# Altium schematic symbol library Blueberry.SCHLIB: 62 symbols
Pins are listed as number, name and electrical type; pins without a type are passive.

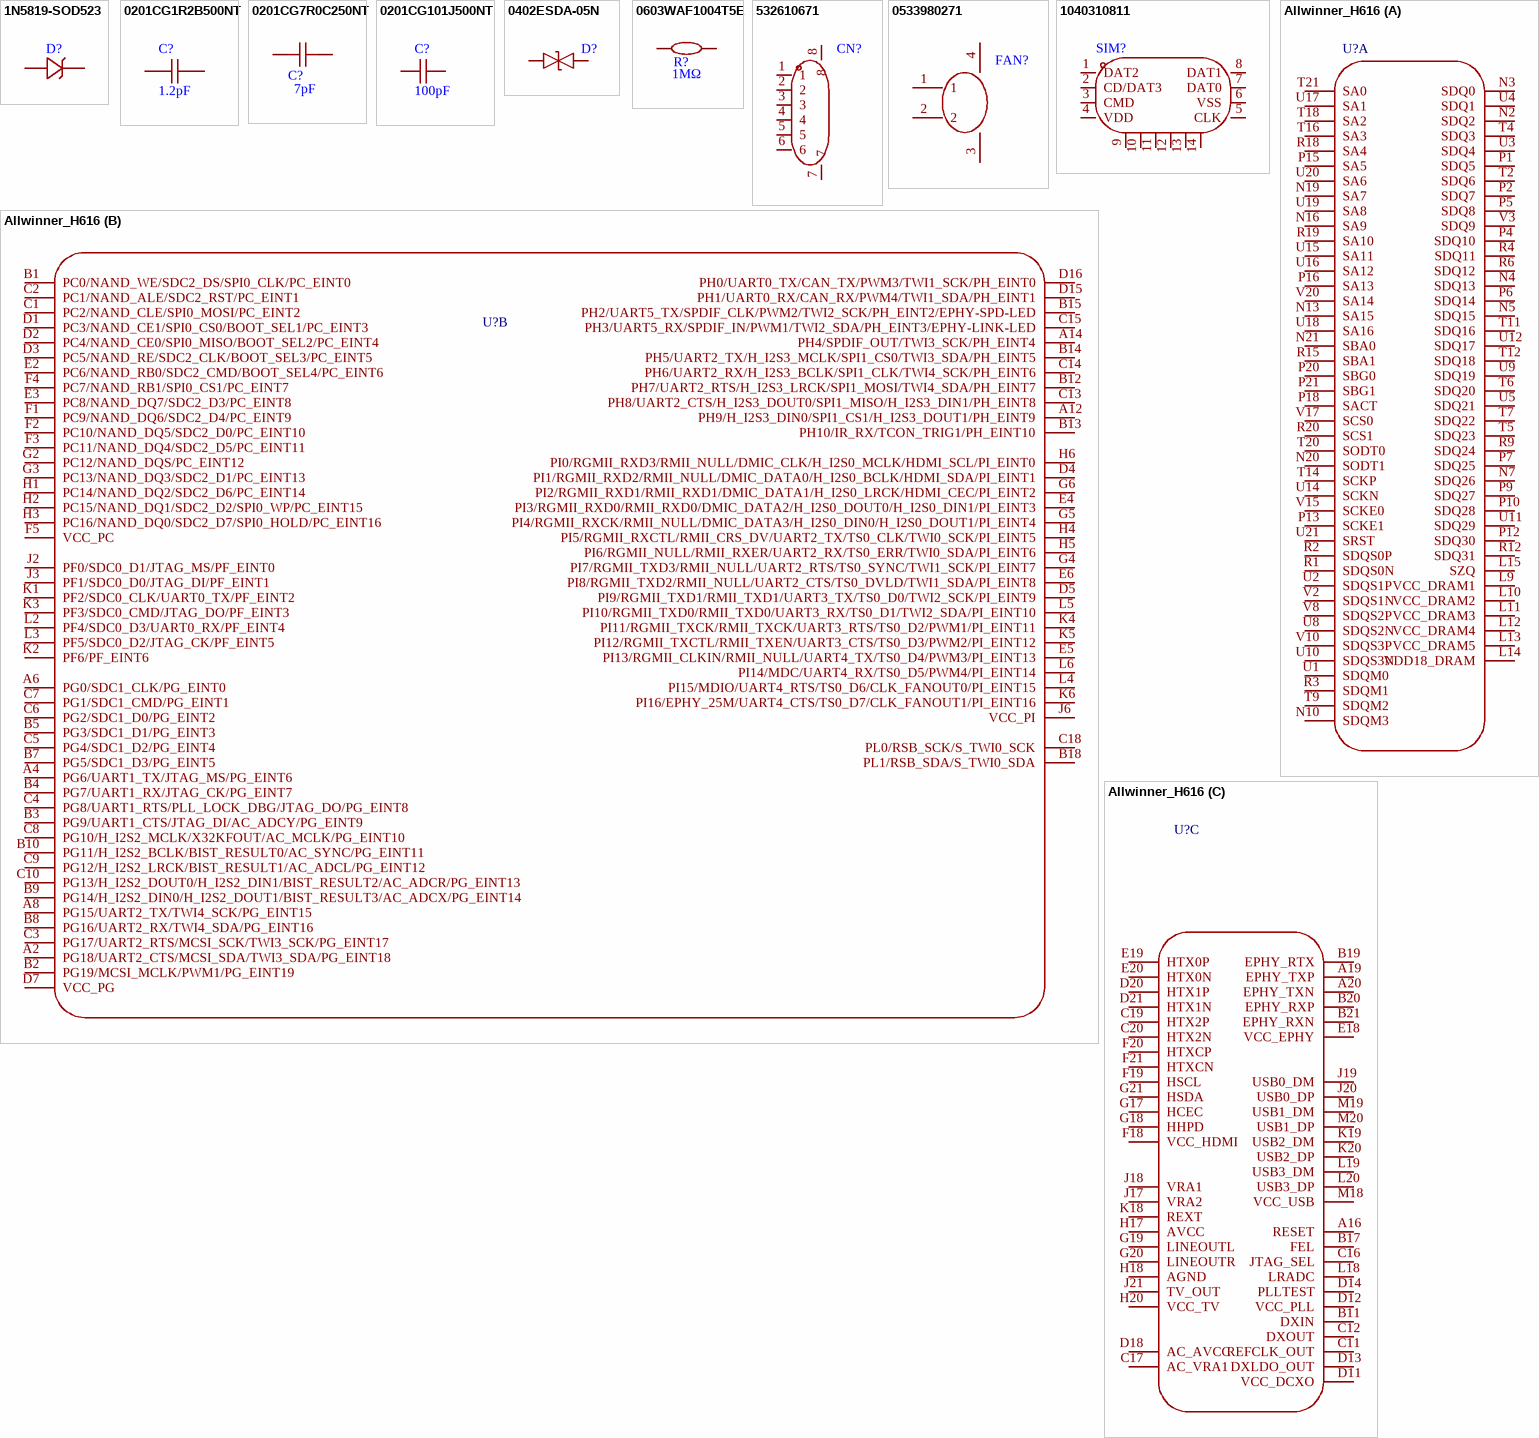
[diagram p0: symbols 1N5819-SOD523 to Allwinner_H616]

## 1N5819-SOD523
designator D?
Symbol: 1N5819-SOD523; Add into BOM: yes
footprint SOD-523_L1.2-W0.8-LS1.6-FD
3D model SOD-523_L1.2-W0.8-H0.7-LS1.6
pins: 1 A, 2 K

## 0201CG1R2B500NT
designator C?, comment 1.2pF
Manufacturer: FH(风华); Symbol: 0201CG1R2B500NT; Add into BOM: yes; Voltage Rated: 50V; Temperature Coefficient: C0G
footprint C0201
3D model C0201_L0.6-W0.3-H0.3
pins: 1, 2

## 0201CG7R0C250NT
designator C?, comment 7pF
Manufacturer: FH(风华); Symbol: 0201CG7R0C250NT; Add into BOM: yes; Voltage Rated: 25V; Temperature Coefficient: C0G
footprint C0201
3D model C0201_L0.6-W0.3-H0.3
pins: 1, 2

## 0201CG101J500NT
designator C?, comment 100pF
Manufacturer: FH(风华); Symbol: 0201CG101J500NT; Add into BOM: yes; Tolerance: ±5%; Voltage Rated: 50V; Temperature Coefficient: C0G
footprint C0201
3D model C0201_L0.6-W0.3-H0.3
pins: 1, 2

## 0402ESDA-05N
designator D?
Manufacturer: BORN伯恩半导体; Symbol: 0402ESDA-05N; Add into BOM: yes; Polarity: Bidirectional; Voltage - Reverse Standoff (Typ): 5V; Voltage - Clamping (Max) @ Ipp: 50V
footprint D0402
3D model D0402_L1.0-W0.5-H0.5
pins: 1, 2

## 0603WAF1004T5E
designator R?, comment 1MΩ
Manufacturer: UNI-ROYAL(厚声); Symbol: 0603WAF1004T5E; Add into BOM: yes; Tolerance: ±1%; Power(Watts): 100mW; Temperature Coefficient: ±100ppm/℃; Overload Voltage (Max): 75V
footprint R0603
3D model R0603
pins: 1, 2

## 532610671
designator CN?
Manufacturer: MOLEX; Symbol: 53261-0671; Device: 532610671; Add into BOM: yes; Pitch: 1.25mm; Pins Structure: 1x6P; Number of PINs Per Row: 6
footprint CONN-SMD_6P-P1.25_53261-0671
3D model CONN-SMD_MX1.25-WS-6P
pins: 1, 2, 3, 4, 5, 6, 7, 8

## 0533980271
designator FAN?
Manufacturer: MOLEX; Symbol: 0533980271; Add into BOM: yes; Pitch: 1.25mm; Pins Structure: 1x2P; Number of PINs Per Row: 2; Gender: 公型插针
footprint CONN-SMD_2P-P1.25_053398-0X71
3D model CONN-SMD_MX1.25-LS-2P
pins: 1, 2, 3, 4

## 1040310811
designator SIM?
Manufacturer: MOLEX; Symbol: 1040310811; Add into BOM: yes; Card Connection Mode: 拔插式; Card Type: MicroSD卡(TF卡); Connector Type: 卡座; Maximum Body Height: 1.42mm
footprint SIM-SMD_8P-1040310811
3D model SIM-SMD_8P-1040310811
pins: 1 DAT2, 2 CD/DAT3, 3 CMD, 4 VDD, 5 CLK, 6 VSS, 7 DAT0, 8 DAT1, 9, 10, 11, 12, 13, 14

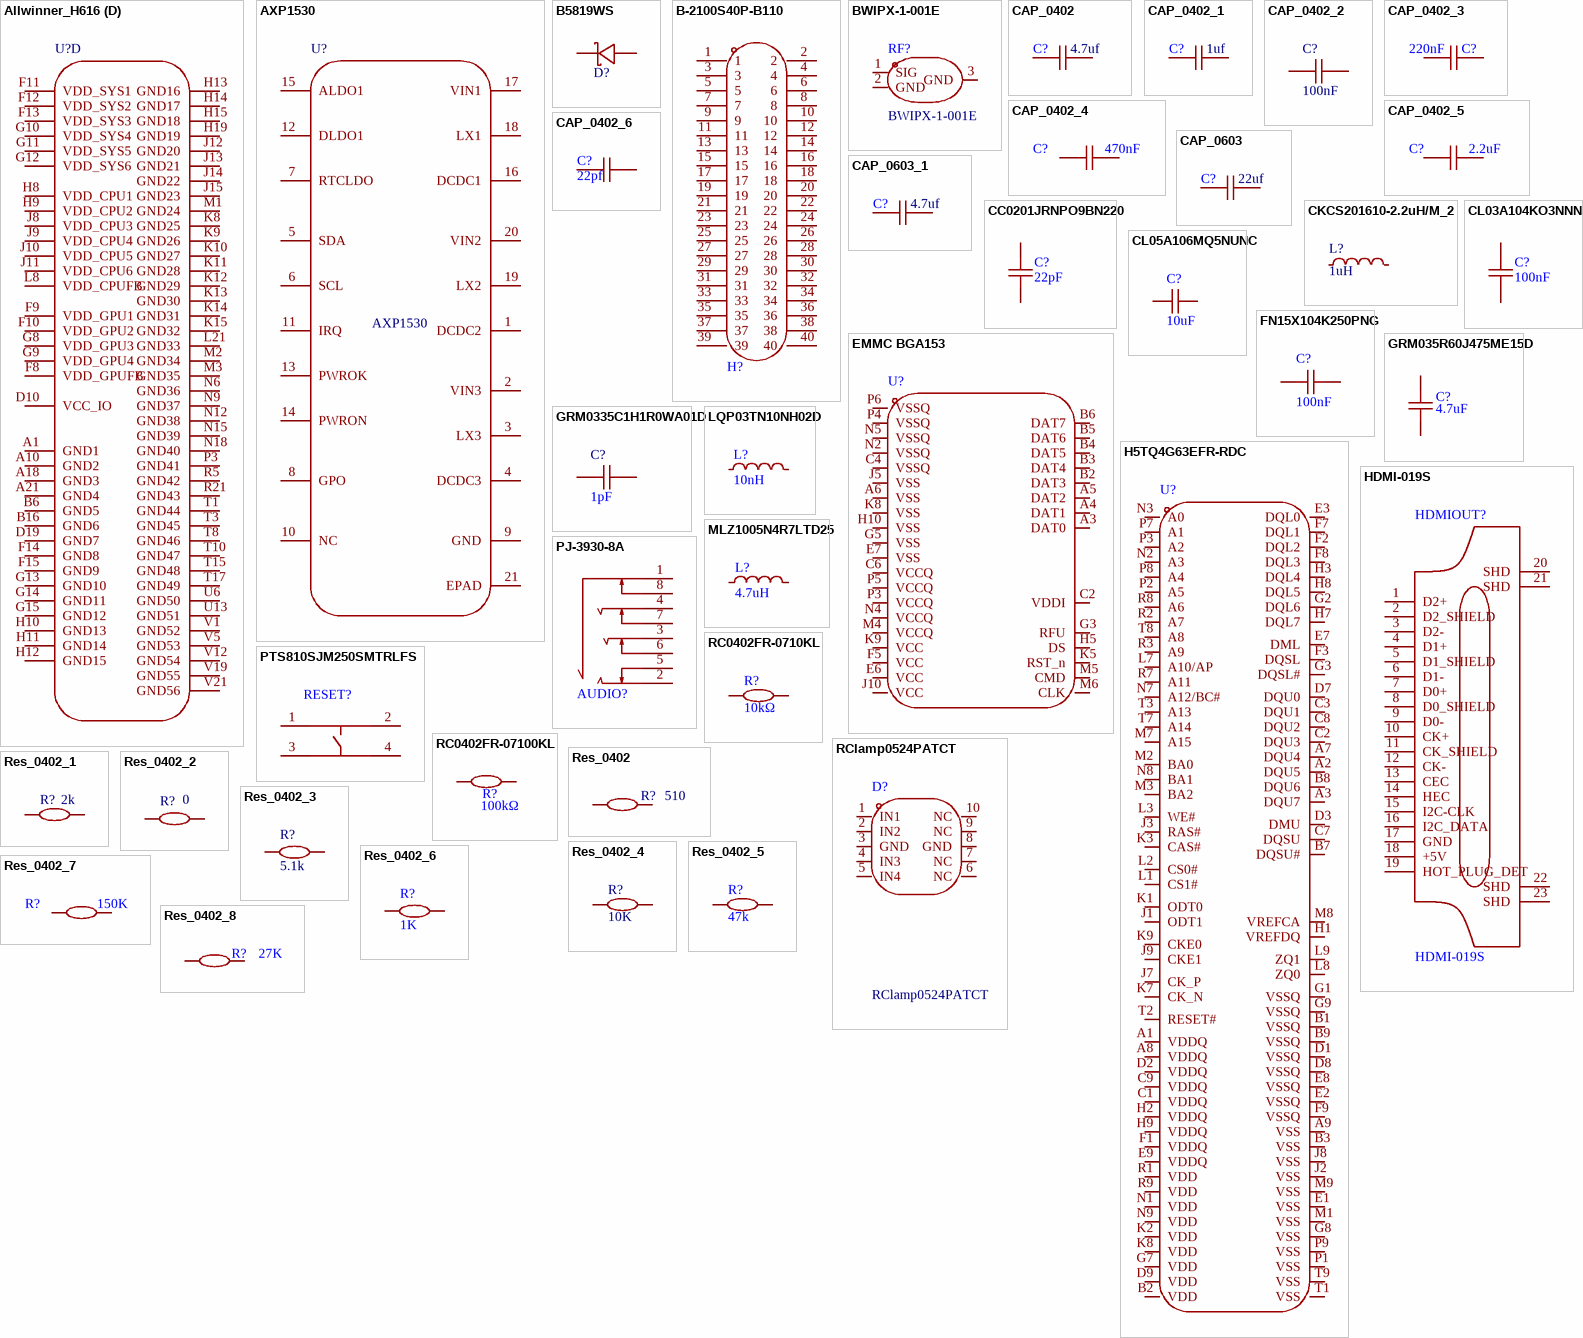
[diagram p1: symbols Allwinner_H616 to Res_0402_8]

## Allwinner_H616
designator U?
Symbol: H616-BGA-190823; Device: Allwinner_H616; Convert to PCB: yes
footprint BGA284P65B1200_1400H125
part A pins: L9 VCC_DRAM1, L10 VCC_DRAM2, L11 VCC_DRAM3, L12 VCC_DRAM4, L13 VCC_DRAM5, L14 VDD18_DRAM, L15 SZQ, N2 SDQ2, N3 SDQ0, N4 SDQ13, N5 SDQ15, N7 SDQ26, N10 SDQM3, N13 SA15, N16 SA9, N19 SA7, N20 SODT1, N21 SBA0, P1 SDQ5, P2 SDQ7, P4 SDQ10, P5 SDQ8, P6 SDQ14, P7 SDQ25, P9 SDQ27, P10 SDQ28, P12 SDQ30, P13 SCKE1, P15 SA5, P16 SA13, P18 SACT, P20 SBG0, P21 SBG1, R1 SDQS0N, R2 SDQS0P, R3 SDQM1, R4 SDQ11, R6 SDQ12, R9 SDQ24, R12 SDQ31, R15 SBA1, R18 SA4, R19 SA10, R20 SCS1, T2 SDQ6, T4 SDQ3, T5 SDQ23, T6 SDQ20, T7 SDQ22, T9 SDQM2, T11 SDQ16, T12 SDQ18, T14 SCKP, T16 SA3, T18 SA2, T20 SODT0, T21 SA0, U1 SDQM0, U2 SDQS1P, U3 SDQ4, U4 SDQ1, U5 SDQ21, U8 SDQS2N, U9 SDQ19, U10 SDQS3N, U11 SDQ29, U12 SDQ17, U14 SCKN, U15 SA11, U16 SA12, U17 SA1, U18 SA16, U19 SA8, U20 SA6, U21 SRST, V2 SDQS1N, V3 SDQ9, V8 SDQS2P, V10 SDQS3P, V15 SCKE0, V17 SCS0, V20 SA14
part B pins: A2 PG18/UART2_CTS/MCSI_SDA/TWI3_SDA/PG_EINT18, A4 PG6/UART1_TX/JTAG_MS/PG_EINT6, A6 PG0/SDC1_CLK/PG_EINT0, A8 PG15/UART2_TX/TWI4_SCK/PG_EINT15, A12 PH9/H_I2S3_DIN0/SPI1_CS1/H_I2S3_DOUT1/PH_EINT9, A14 PH4/SPDIF_OUT/TWI3_SCK/PH_EINT4, B1 PC0/NAND_WE/SDC2_DS/SPI0_CLK/PC_EINT0, B2 PG19/MCSI_MCLK/PWM1/PG_EINT19, B3 PG9/UART1_CTS/JTAG_DI/AC_ADCY/PG_EINT9, B4 PG7/UART1_RX/JTAG_CK/PG_EINT7, B5 PG3/SDC1_D1/PG_EINT3, B7 PG5/SDC1_D3/PG_EINT5, B8 PG16/UART2_RX/TWI4_SDA/PG_EINT16, B9 PG14/H_I2S2_DIN0/H_I2S2_DOUT1/BIST_RESULT3/AC_ADCX/PG_EINT14, B10 PG11/H_I2S2_BCLK/BIST_RESULT0/AC_SYNC/PG_EINT11, B12 PH7/UART2_RTS/H_I2S3_LRCK/SPI1_MOSI/TWI4_SDA/PH_EINT7, B13 PH10/IR_RX/TCON_TRIG1/PH_EINT10, B14 PH5/UART2_TX/H_I2S3_MCLK/SPI1_CS0/TWI3_SDA/PH_EINT5, B15 PH2/UART5_TX/SPDIF_CLK/PWM2/TWI2_SCK/PH_EINT2/EPHY-SPD-LED, B18 PL1/RSB_SDA/S_TWI0_SDA, C1 PC2/NAND_CLE/SPI0_MOSI/PC_EINT2, C2 PC1/NAND_ALE/SDC2_RST/PC_EINT1, C3 PG17/UART2_RTS/MCSI_SCK/TWI3_SCK/PG_EINT17, C4 PG8/UART1_RTS/PLL_LOCK_DBG/JTAG_DO/PG_EINT8, C5 PG4/SDC1_D2/PG_EINT4, C6 PG2/SDC1_D0/PG_EINT2, C7 PG1/SDC1_CMD/PG_EINT1, C8 PG10/H_I2S2_MCLK/X32KFOUT/AC_MCLK/PG_EINT10, C9 PG12/H_I2S2_LRCK/BIST_RESULT1/AC_ADCL/PG_EINT12, C10 PG13/H_I2S2_DOUT0/H_I2S2_DIN1/BIST_RESULT2/AC_ADCR/PG_EINT13, C13 PH8/UART2_CTS/H_I2S3_DOUT0/SPI1_MISO/H_I2S3_DIN1/PH_EINT8, C14 PH6/UART2_RX/H_I2S3_BCLK/SPI1_CLK/TWI4_SCK/PH_EINT6, C15 PH3/UART5_RX/SPDIF_IN/PWM1/TWI2_SDA/PH_EINT3/EPHY-LINK-LED, C18 PL0/RSB_SCK/S_TWI0_SCK, D1 PC3/NAND_CE1/SPI0_CS0/BOOT_SEL1/PC_EINT3, D2 PC4/NAND_CE0/SPI0_MISO/BOOT_SEL2/PC_EINT4, D3 PC5/NAND_RE/SDC2_CLK/BOOT_SEL3/PC_EINT5, D4 PI1/RGMII_RXD2/RMII_NULL/DMIC_DATA0/H_I2S0_BCLK/HDMI_SDA/PI_EINT1, D5 PI9/RGMII_TXD1/RMII_TXD1/UART3_TX/TS0_D0/TWI2_SCK/PI_EINT9, D7 VCC_PG, D15 PH1/UART0_RX/CAN_RX/PWM4/TWI1_SDA/PH_EINT1, D16 PH0/UART0_TX/CAN_TX/PWM3/TWI1_SCK/PH_EINT0, E2 PC6/NAND_RB0/SDC2_CMD/BOOT_SEL4/PC_EINT6, E3 PC8/NAND_DQ7/SDC2_D3/PC_EINT8, E4 PI3/RGMII_RXD0/RMII_RXD0/DMIC_DATA2/H_I2S0_DOUT0/H_I2S0_DIN1/PI_EINT3, E5 PI13/RGMII_CLKIN/RMII_NULL/UART4_TX/TS0_D4/PWM3/PI_EINT13, E6 PI8/RGMII_TXD2/RMII_NULL/UART2_CTS/TS0_DVLD/TWI1_SDA/PI_EINT8, F1 PC9/NAND_DQ6/SDC2_D4/PC_EINT9, F2 PC10/NAND_DQ5/SDC2_D0/PC_EINT10, F3 PC11/NAND_DQ4/SDC2_D5/PC_EINT11, F4 PC7/NAND_RB1/SPI0_CS1/PC_EINT7, F5 VCC_PC, G2 PC12/NAND_DQS/PC_EINT12, G3 PC13/NAND_DQ3/SDC2_D1/PC_EINT13, G4 PI7/RGMII_TXD3/RMII_NULL/UART2_RTS/TS0_SYNC/TWI1_SCK/PI_EINT7, G5 PI4/RGMII_RXCK/RMII_NULL/DMIC_DATA3/H_I2S0_DIN0/H_I2S0_DOUT1/PI_EINT4, G6 PI2/RGMII_RXD1/RMII_RXD1/DMIC_DATA1/H_I2S0_LRCK/HDMI_CEC/PI_EINT2, H1 PC14/NAND_DQ2/SDC2_D6/PC_EINT14, H2 PC15/NAND_DQ1/SDC2_D2/SPI0_WP/PC_EINT15, H3 PC16/NAND_DQ0/SDC2_D7/SPI0_HOLD/PC_EINT16, H4 PI5/RGMII_RXCTL/RMII_CRS_DV/UART2_TX/TS0_CLK/TWI0_SCK/PI_EINT5, H5 PI6/RGMII_NULL/RMII_RXER/UART2_RX/TS0_ERR/TWI0_SDA/PI_EINT6, H6 PI0/RGMII_RXD3/RMII_NULL/DMIC_CLK/H_I2S0_MCLK/HDMI_SCL/PI_EINT0, J2 PF0/SDC0_D1/JTAG_MS/PF_EINT0, J3 PF1/SDC0_D0/JTAG_DI/PF_EINT1, J6 VCC_PI, K1 PF2/SDC0_CLK/UART0_TX/PF_EINT2, K2 PF6/PF_EINT6, K3 PF3/SDC0_CMD/JTAG_DO/PF_EINT3, K4 PI11/RGMII_TXCK/RMII_TXCK/UART3_RTS/TS0_D2/PWM1/PI_EINT11, K5 PI12/RGMII_TXCTL/RMII_TXEN/UART3_CTS/TS0_D3/PWM2/PI_EINT12, K6 PI16/EPHY_25M/UART4_CTS/TS0_D7/CLK_FANOUT1/PI_EINT16, L2 PF4/SDC0_D3/UART0_RX/PF_EINT4, L3 PF5/SDC0_D2/JTAG_CK/PF_EINT5, L4 PI15/MDIO/UART4_RTS/TS0_D6/CLK_FANOUT0/PI_EINT15, L5 PI10/RGMII_TXD0/RMII_TXD0/UART3_RX/TS0_D1/TWI2_SDA/PI_EINT10, L6 PI14/MDC/UART4_RX/TS0_D5/PWM4/PI_EINT14
part C pins: A16 RESET, A19 EPHY_TXP, A20 EPHY_TXN, B11 DXIN, B17 FEL, B19 EPHY_RTX, B20 EPHY_RXP, B21 EPHY_RXN, C11 REFCLK_OUT, C12 DXOUT, C16 JTAG_SEL, C17 AC_VRA1, C19 HTX2P, C20 HTX2N, D11 VCC_DCXO, D12 VCC_PLL, D13 DXLDO_OUT, D14 PLLTEST, D18 AC_AVCC, D20 HTX1P, D21 HTX1N, E18 VCC_EPHY, E19 HTX0P, E20 HTX0N, F18 VCC_HDMI, F19 HSCL, F20 HTXCP, F21 HTXCN, G17 HCEC, G18 HHPD, G19 LINEOUTL, G20 LINEOUTR, G21 HSDA, H17 AVCC, H18 AGND, H20 VCC_TV, J17 VRA2, J18 VRA1, J19 USB0_DM, J20 USB0_DP, J21 TV_OUT, K18 REXT, K19 USB2_DM, K20 USB2_DP, L18 LRADC, L19 USB3_DM, L20 USB3_DP, M18 VCC_USB, M19 USB1_DM, M20 USB1_DP
part D pins: A1 GND1, A10 GND2, A18 GND3, A21 GND4, B6 GND5, B16 GND6, D10 VCC_IO, D19 GND7, F8 VDD_GPUFB, F9 VDD_GPU1, F10 VDD_GPU2, F11 VDD_SYS1, F12 VDD_SYS2, F13 VDD_SYS3, F14 GND8, F15 GND9, G8 VDD_GPU3, G9 VDD_GPU4, G10 VDD_SYS4, G11 VDD_SYS5, G12 VDD_SYS6, G13 GND10, G14 GND11, G15 GND12, H8 VDD_CPU1, H9 VDD_CPU2, H10 GND13, H11 GND14, H12 GND15, H13 GND16, H14 GND17, H15 GND18, H19 GND19, J8 VDD_CPU3, J9 VDD_CPU4, J10 VDD_CPU5, J11 VDD_CPU6, J12 GND20, J13 GND21, J14 GND22, J15 GND23, K8 GND25, K9 GND26, K10 GND27, K11 GND28, K12 GND29, K13 GND30, K14 GND31, K15 GND32, L8 VDD_CPUFB, L21 GND33, M1 GND24, M2 GND34, M3 GND35, N6 GND36, N9 GND37, N12 GND38, N15 GND39, N18 GND40, P3 GND41, R5 GND42, R21 GND43, T1 GND44, T3 GND45, T8 GND46, T10 GND47, T15 GND48, T17 GND49, U6 GND50, U13 GND51, V1 GND52, V5 GND53, V12 GND54, V19 GND55, V21 GND56

## AXP1530
designator U?, comment Device: AXP1530  (hidden comment: AXP313A)
Add into BOM: yes; PCB Footprint: QFN21P40B300_300H78
footprint WQFN-20_L3.0-W3.0-P0.40-BL-EP
pins: 1 DCDC2, 2 VIN3, 3 LX3, 4 DCDC3, 5 SDA, 6 SCL, 7 RTCLDO, 8 GPO, 9 GND, 10 NC, 11 IRQ, 12 DLDO1, 13 PWROK, 14 PWRON, 15 ALDO1, 16 DCDC1, 17 VIN1, 18 LX1, 19 LX2, 20 VIN2, 21 EPAD

## B5819WS
designator D?
Manufacturer: CJ（江苏长电/长晶）; Symbol: B5819WS_C22624; Device: B5819WS; Add into BOM: yes; Reverse Voltage (Vr): 40V; Average Rectified Current (Io): 1A; Forward Voltage (Vf@If): 600mV@1A
footprint SOD-323_L1.8-W1.3-LS2.5-NSK
3D model SOD-323_L1.7-W1.3-H1.1-LS2.5
pins: 1 K, 2 A

## B-2100S40P-B110
designator H?  (value not drawn)
Manufacturer: Ckmtw(灿科盟); Symbol: 210S-2*20P L=11.6MMGold-plated black; Add into BOM: yes; Pitch: 2.54mm; Pin Structure: 2x20P
footprint HDR-TH_40P-P2.54-V-M-R2-C20-S2.54
3D model HDR-TH_40P-P2.54-M-LI-2X20P
pins: 1, 2, 3, 4, 5, 6, 7, 8, 9, 10, 11, 12, 13, 14, 15, 16, 17, 18, 19, 20, 21, 22, 23, 24, 25, 26, 27, 28, 29, 30, 31, 32, 33, 34, 35, 36, 37, 38, 39, 40

## BWIPX-1-001E
designator RF?
Manufacturer: BATWIRELESS(蝙蝠无线); Add into BOM: yes; Connector Type: 板端; RF Series: IPEX; Interface Type: 内针; Number of Ports: 1; Impedance: 50Ω; Frequency-Max: 6GHz
footprint IPEX-SMD_BWIPX-1-001E
3D model IPEX-SMD_BWIPX-1-001E
pins: 1 SIG, 2 GND, 3 GND

## CAP_0402
designator C?  value 4.7uf
Symbol: C1210X7R475K630NT; Device: CAP_0402; Convert to PCB: yes
footprint C0402-NSK
3D model C0402
pins: 1, 2

## CAP_0402_1
designator C?  value 1uf
Symbol: C1210X7R475K630NT; Device: CAP_0402; Convert to PCB: yes
footprint C0402-NSK
3D model C0402
pins: 1, 2

## CAP_0402_2
designator C?  value 100nF
Symbol: C1210X7R475K630NT; Device: CAP_0402; Convert to PCB: yes
footprint C0402-NSK
3D model C0402
pins: 1, 2

## CAP_0402_3
designator C?  value 220nF
Symbol: C1210X7R475K630NT; Device: CAP_0402; Convert to PCB: yes
footprint C0402-NSK
3D model C0402
pins: 1, 2

## CAP_0402_4
designator C?  value 470nF
Symbol: C1210X7R475K630NT; Device: CAP_0402; Convert to PCB: yes
footprint C0402-NSK
3D model C0402
pins: 1, 2

## CAP_0402_5
designator C?  value 2.2uF
Symbol: C1210X7R475K630NT; Device: CAP_0402; Convert to PCB: yes
footprint C0402-NSK
3D model C0402
pins: 1, 2

## CAP_0402_6
designator C?  value 22pf
Symbol: C1210X7R475K630NT; Device: CAP_0402; Convert to PCB: yes
footprint C0402-NSK
3D model C0402
pins: 1, 2

## CAP_0603
designator C?  value 22uf
Symbol: C1210X7R475K630NT; Device: CAP_0603; Convert to PCB: yes
footprint C0603 NSK
3D model C0603_L1.6-W0.8-H0.8
pins: 1, 2

## CAP_0603_1
designator C?  value 4.7uf
Symbol: C1210X7R475K630NT; Device: CAP_0603; Convert to PCB: yes
footprint C0603 NSK
3D model C0603_L1.6-W0.8-H0.8
pins: 1, 2

## CC0201JRNPO9BN220
designator C?, comment 22pF
Manufacturer: YAGEO(国巨); Symbol: CC0201JRNPO9BN220; Add into BOM: yes; Tolerance: ±5%; Voltage Rated: 50V; Temperature Coefficient: NP0
footprint C0201
3D model C0201_L0.6-W0.3-H0.3
pins: 1, 2

## CKCS201610-2.2uH/M_2
designator L?  value 1uH
Manufacturer: CENKER(岑科); Manufacturer Part: CKCS201610-2.2uH/M; Symbol: CKCS201610-2.2UH/M-N; Device: CKCS201610-2.2uH/M_2; Add into BOM: yes; Tolerance: ±20%; Rated Current: 1.1A; DC Resistance (DCR): 264mΩ
footprint IND-SMD_L2.0-W1.6_1
3D model IND-SMD_L2.0-W1.6-H1.1
pins: 1, 2

## CL03A104KO3NNNC
designator C?, comment 100nF
Manufacturer: SAMSUNG(三星); Symbol: CL03A104KO3NNNC; Add into BOM: yes; Tolerance: ±10%; Voltage Rated: 16V; Temperature Coefficient: X5R
footprint C0201
3D model C0201_L0.6-W0.3-H0.3
pins: 1, 2

## CL05A106MQ5NUNC
designator C?, comment 10uF
Manufacturer: SAMSUNG(三星); Symbol: CL05A106MQ5NUNC; Add into BOM: yes; Tolerance: ±20%; Voltage Rated: 6.3V; Temperature Coefficient: X5R
footprint C0402
3D model C0402_L1.0-W0.5-H0.5
pins: 1, 2

## EMMC BGA153
designator U?
Manufacturer: Kingston(金士顿); Manufacturer Part: EMMC04G-M627-A01; Symbol: EMMC BGA153; Pin Type: IN; Add into BOM: yes
footprint FBGA-153_L13.0-W11.5
pins: A3 DAT0, A4 DAT1, A5 DAT2, A6 VSS, B2 DAT3, B3 DAT4, B4 DAT5, B5 DAT6, B6 DAT7, C2 VDDI, C4 VSSQ, C6 VCCQ, E6 VCC, E7 VSS, F5 VCC, G3 RFU, G5 VSS, H5 DS, H10 VSS, J5 VSS, J10 VCC, K5 RST_n, K8 VSS, K9 VCC, M4 VCCQ, M5 CMD, M6 CLK, N2 VSSQ, N4 VCCQ, N5 VSSQ, P3 VCCQ, P4 VSSQ, P5 VCCQ, P6 VSSQ

## FN15X104K250PNG
designator C?  value 100nF
Manufacturer: PSA(信昌电陶); Symbol: FN15X104K250PNG; Add into BOM: yes; Tolerance: ±10%; Voltage Rated: 25V; Temperature Coefficient: X7R
footprint C0402-NSK
3D model C0402_L1.0-W0.5-H0.5
pins: 1, 2

## GRM035R60J475ME15D
designator C?, comment 4.7uF
Manufacturer: muRata(村田); Symbol: GRM035R60J475ME15D; Add into BOM: yes; Tolerance: ±20%; Voltage Rated: 6.3V; Temperature Coefficient: X5R
footprint C0201
3D model C0201_L0.6-W0.3-H0.3
pins: 1, 2

## GRM0335C1H1R0WA01D
designator C?, comment 1pF
Manufacturer: muRata(村田); Symbol: GRM0335C1H1R0WA01D; Add into BOM: yes; Voltage Rated: 50V; Temperature Coefficient: C0G
footprint C0201
3D model C0201_L0.6-W0.3-H0.3
pins: 1, 2

## H5TQ4G63EFR-RDC
designator U?
Manufacturer: HYNIX(海力士); Symbol: H5TQ4G63EFR-RDC; Pin Type: IN; Add into BOM: yes
footprint FBGA96
pins: A1 VDDQ, A2 DQU5, A3 DQU7, A7 DQU4, A8 VDDQ, A9 VSS, B1 VSSQ, B2 VDD, B3 VSS, B7 DQSU#, B8 DQU6, B9 VSSQ, C1 VDDQ, C2 DQU3, C3 DQU1, C7 DQSU, C8 DQU2, C9 VDDQ, D1 VSSQ, D2 VDDQ, D3 DMU, D7 DQU0, D8 VSSQ, D9 VDD, E1 VSS, E2 VSSQ, E3 DQL0, E7 DML, E8 VSSQ, E9 VDDQ, F1 VDDQ, F2 DQL2, F3 DQSL, F7 DQL1, F8 DQL3, F9 VSSQ, G1 VSSQ, G2 DQL6, G3 DQSL#, G7 VDD, G8 VSS, G9 VSSQ, H1 VREFDQ, H2 VDDQ, H3 DQL4, H7 DQL7, H8 DQL5, H9 VDDQ, J1 ODT1, J2 VSS, J3 RAS#, J7 CK_P, J8 VSS, J9 CKE1, K1 ODT0, K2 VDD, K3 CAS#, K7 CK_N, K8 VDD, K9 CKE0, L1 CS1#, L2 CS0#, L3 WE#, L7 A10/AP, L8 ZQ0, L9 ZQ1, M1 VSS, M2 BA0, M3 BA2, M7 A15, M8 VREFCA, M9 VSS, N1 VDD, N2 A3, N3 A0, N7 A12/BC#, N8 BA1, N9 VDD, P1 VSS, P2 A5, P3 A2, P7 A1, P8 A4, P9 VSS, R1 VDD, R2 A7, R3 A9, R7 A11, R8 A6, R9 VDD, T1 VSS, T2 RESET#, T3 A13, T7 A14, T8 A8, T9 VSS

## HDMI-019S
designator HDMIOUT?  Manufacturer Part: HDMI-019S
Manufacturer: SOFNG(硕方); Add into BOM: yes; Connector Type: HDMI; Gender: 母; Current Rating (Max): 500mA
footprint HDMI-SMD_HDMI-019S
3D model HDMI-SMD_HDMI-019S
pins: 1 D2+, 2 D2_SHIELD, 3 D2-, 4 D1+, 5 D1_SHIELD, 6 D1-, 7 D0+, 8 D0_SHIELD, 9 D0-, 10 CK+, 11 CK_SHIELD, 12 CK-, 13 CEC, 14 HEC, 15 I2C-CLK, 16 I2C_DATA, 17 GND, 18 +5V, 19 HOT_PLUG_DET, 20 SHD, 21 SHD, 22 SHD, 23 SHD

## LQP03TN10NH02D
designator L?, comment 10nH
Manufacturer: muRata(村田); Symbol: LQP03TN10NH02D; Add into BOM: yes; Tolerance: ±3%; Rated Current: 250mA; DC Resistance (DCR): 700mΩ; Q @ Freq: 14@500MHz; Frequency - Self Resonant: 3.2GHz
footprint L0201
3D model L0201-RD
pins: 1, 2

## MLZ1005N4R7LTD25
designator L?, comment 4.7uH
Manufacturer: TDK; Symbol: MLZ1005N4R7LTD25; Add into BOM: yes; Tolerance: ±20%
footprint L0402
3D model L0402_L1.0-W0.5-H0.5_BEAD
pins: 1, 2

## PJ-3930-8A
designator AUDIO?
Manufacturer: 韩国韩荣; Symbol: PJ-3930-8A; Add into BOM: yes; Connector Type: 3.5mm耳机座; Current Rating (Max): 500mA; Voltage Rating (Max): 30V
footprint AUDIO-TH_PJ-3930-8A
3D model AUDIO-TH_PJ-3930-8A
pins: 1, 2, 3, 4, 5, 6, 7, 8

## PTS810SJM250SMTRLFS
designator RESET?  (value not drawn)
Manufacturer: C&K; Add into BOM: yes; Contact Current: 50mA; Voltage Rating (DC): 16V; Circuit: 单刀单掷; Actuator Style: 圆形按钮; Operating Force: 160gf; Pin Style: J型引脚; Switch Length: 4.2mm; Switch Width: 3.2mm; Switch Height: 2.5mm
footprint KEY-SMD_4P-L4.2-W3.2-P2.20-LS4.6
3D model KEY-SMD_4P-L4.2-W3.2-H2.5-LS4.6-P2.2
pins: 1, 2, 3, 4

## RC0402FR-0710KL
designator R?, comment 10kΩ
Manufacturer: YAGEO(国巨); Symbol: RC0402FR-0710KL; Add into BOM: yes; Tolerance: ±1%; Power(Watts): 62.5mW; Temperature Coefficient: ±100ppm/℃; Overload Voltage (Max): 50V
footprint R0402
3D model R0402_L1.0-W0.5-H0.5
pins: 1, 2

## RC0402FR-07100KL
designator R?, comment 100kΩ
Manufacturer: YAGEO(国巨); Symbol: RC0402FR-07100KL; Add into BOM: yes; Tolerance: ±1%; Power(Watts): 62.5mW; Temperature Coefficient: ±100ppm/℃; Overload Voltage (Max): 50V
footprint R0402
3D model R0402_L1.0-W0.5-H0.5
pins: 1, 2

## RClamp0524PATCT
designator D?  Manufacturer Part: RClamp0524PATCT
Manufacturer: SEMTECH; Add into BOM: yes
footprint SLP2510P8_L2.5-W1.0-P0.50-BL
3D model SLP2510-8P_L2.5-W1.0-H0.5
pins: 1 IN1, 2 IN2, 3 GND, 4 IN3, 5 IN4, 6 NC, 7 NC, 8 GND, 9 NC, 10 NC

## Res_0402
designator R?  value 510
Symbol: 电阻; Device: Res_0402; Convert to PCB: yes
footprint R0402-NSK_2
3D model R0402_L1.0-W0.5-H0.4
pins: 1, 2

## Res_0402_1
designator R?  value 2k
Symbol: 电阻; Device: Res_0402; Convert to PCB: yes
footprint R0402-NSK_2
3D model R0402_L1.0-W0.5-H0.4
pins: 1, 2

## Res_0402_2
designator R?  value 0
Symbol: 电阻; Device: Res_0402; Convert to PCB: yes
footprint R0402-NSK_2
3D model R0402_L1.0-W0.5-H0.4
pins: 1, 2

## Res_0402_3
designator R?  value 5.1k
Symbol: 电阻; Device: Res_0402; Convert to PCB: yes
footprint R0402-NSK_2
3D model R0402_L1.0-W0.5-H0.4
pins: 1, 2

## Res_0402_4
designator R?  value 10K
Symbol: 电阻; Device: Res_0402; Convert to PCB: yes
footprint R0402-NSK_2
3D model R0402_L1.0-W0.5-H0.4
pins: 1, 2

## Res_0402_5
designator R?  value 47k
Symbol: 电阻; Device: Res_0402; Convert to PCB: yes
footprint R0402-NSK_2
3D model R0402_L1.0-W0.5-H0.4
pins: 1, 2

## Res_0402_6
designator R?  value 1K
Symbol: 电阻; Device: Res_0402; Convert to PCB: yes
footprint R0402-NSK_2
3D model R0402_L1.0-W0.5-H0.4
pins: 1, 2

## Res_0402_7
designator R?  value 150K
Symbol: 电阻; Device: Res_0402; Convert to PCB: yes
footprint R0402-NSK_2
3D model R0402_L1.0-W0.5-H0.4
pins: 1, 2

## Res_0402_8
designator R?  value 27K
Symbol: 电阻; Device: Res_0402; Convert to PCB: yes
footprint R0402-NSK_2
3D model R0402_L1.0-W0.5-H0.4
pins: 1, 2

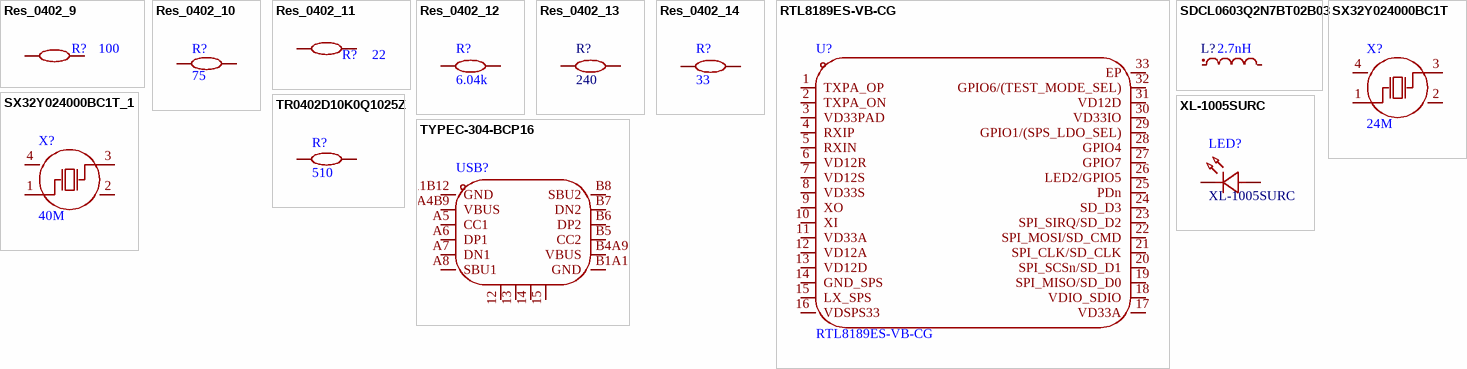
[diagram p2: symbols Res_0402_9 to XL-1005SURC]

## Res_0402_9
designator R?  value 100
Symbol: 电阻; Device: Res_0402; Convert to PCB: yes
footprint R0402-NSK_2
3D model R0402_L1.0-W0.5-H0.4
pins: 1, 2

## Res_0402_10
designator R?  value 75
Symbol: 电阻; Device: Res_0402; Convert to PCB: yes
footprint R0402-NSK_2
3D model R0402_L1.0-W0.5-H0.4
pins: 1, 2

## Res_0402_11
designator R?  value 22
Symbol: 电阻; Device: Res_0402; Convert to PCB: yes
footprint R0402-NSK_2
3D model R0402_L1.0-W0.5-H0.4
pins: 1, 2

## Res_0402_12
designator R?  value 6.04k
Symbol: 电阻; Device: Res_0402; Convert to PCB: yes
footprint R0402-NSK_2
3D model R0402_L1.0-W0.5-H0.4
pins: 1, 2

## Res_0402_13
designator R?  value 240
Symbol: 电阻; Device: Res_0402; Convert to PCB: yes
footprint R0402-NSK_2
3D model R0402_L1.0-W0.5-H0.4
pins: 1, 2

## Res_0402_14
designator R?  value 33
Symbol: 电阻; Device: Res_0402; Convert to PCB: yes
footprint R0402-NSK_2
3D model R0402_L1.0-W0.5-H0.4
pins: 1, 2

## RTL8189ES-VB-CG
designator U?
Manufacturer: REALTEK(瑞昱); Add into BOM: yes
footprint QFN-32_L5.0-W5.0-P0.50-TL-EP3.5
3D model QFN-32_L5.0-W5.0-H1.0-P0.50-TL-EP3.5
pins: 1 TXPA_OP, 2 TXPA_ON, 3 VD33PAD, 4 RXIP, 5 RXIN, 6 VD12R, 7 VD12S, 8 VD33S, 9 XO, 10 XI, 11 VD33A, 12 VD12A, 13 VD12D, 14 GND_SPS, 15 LX_SPS, 16 VDSPS33, 17 VD33A, 18 VDIO_SDIO, 19 SPI_MISO/SD_D0, 20 SPI_SCSn/SD_D1, 21 SPI_CLK/SD_CLK, 22 SPI_MOSI/SD_CMD, 23 SPI_SIRQ/SD_D2, 24 SD_D3, 25 PDn, 26 LED2/GPIO5, 27 GPIO7, 28 GPIO4, 29 GPIO1/(SPS_LDO_SEL), 30 VD33IO, 31 VD12D, 32 GPIO6/(TEST_MODE_SEL), 33 EP

## SDCL0603Q2N7BT02B03
designator L?, comment 2.7nH
Manufacturer: Sunlord(顺络); Symbol: SDCL0603Q2N7BT02B03; Add into BOM: yes; Rated Current: 500mA; DC Resistance (DCR): 200mΩ; Q @ Freq: 13@500MHz; Frequency - Self Resonant: 500MHz
footprint L0201-RD
3D model L0201-RD
pins: 1, 2

## SX32Y024000BC1T
designator X?, comment 24M
Manufacturer: TKD(泰晶); Symbol: SX32Y024000BC1T; Add into BOM: yes
footprint OSC-SMD_4P-L2.0-W1.6-BL
3D model OSC-SMD_4P-L3.2-W2.5-H1.0
pins: 1 OSC1, 2 GND, 3 OSC2, 4 GND

## SX32Y024000BC1T_1
designator X?, comment 40M
Manufacturer: TKD(泰晶); Symbol: SX32Y024000BC1T; Add into BOM: yes
footprint osc-smd_4p-l2.0-w1.6-bl
3D model OSC-SMD_4P-L3.2-W2.5-H1.0
pins: 1 OSC1, 2 GND, 3 OSC2, 4 GND

## TR0402D10K0Q1025Z
designator R?  value 510
Manufacturer: EVER OHMS(天二科技); Symbol: TR0402D10KQ1025; Device: TR0402D10K0Q1025Z; Add into BOM: yes; Tolerance: ±0.5%; Power(Watts): 63mW; Temperature Coefficient: ±25ppm/; Overload Voltage (Max): 25V
footprint R0402-NSK_2
3D model R0402_L1.0-W0.5-H0.5
pins: 1, 2

## TYPEC-304-BCP16
designator USB?
Manufacturer: XUNPU; Symbol: TYPEC-304-BCP16; Pin Type: IN; Add into BOM: yes
footprint USB-C-SMD_TYPEC-304-BCP16-1
3D model USB-C-SMD_TYPEC-304-BCP16
pins: 12 1, 13 2, 14 3, 15 4, A1B12 GND, A4B9 VBUS, A5 CC1, A6 DP1, A7 DN1, A8 SBU1, B1A12 GND, B4A9 VBUS, B5 CC2, B6 DP2, B7 DN2, B8 SBU2

## XL-1005SURC
designator LED?
Manufacturer: XINGLIGHT(成兴光); Add into BOM: yes; Emitted Color: 红灯; Lens Color: 无色透明; Dominant Wavelength: 620nm; Peak Wavelength: 625nm; Color Temperature: 6000K~7000K; Forward Current: 25mA; Power Dissipation: 55mW; Viewing Angle: 120°; Mounting Sytle: 正贴
footprint LED0402-R-RD_RED
3D model LED0402_L1.0-W0.5-H0.4
pins: 1 K, 2 A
